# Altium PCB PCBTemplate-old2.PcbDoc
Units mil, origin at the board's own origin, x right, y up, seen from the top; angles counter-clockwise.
Board outline 6000 x 4000 mil, 4 copper layers (Top Layer, Internal Plane 1, Internal Plane 2, Bottom Layer); 0 components, 0 nets, 1 pads, 0 vias.
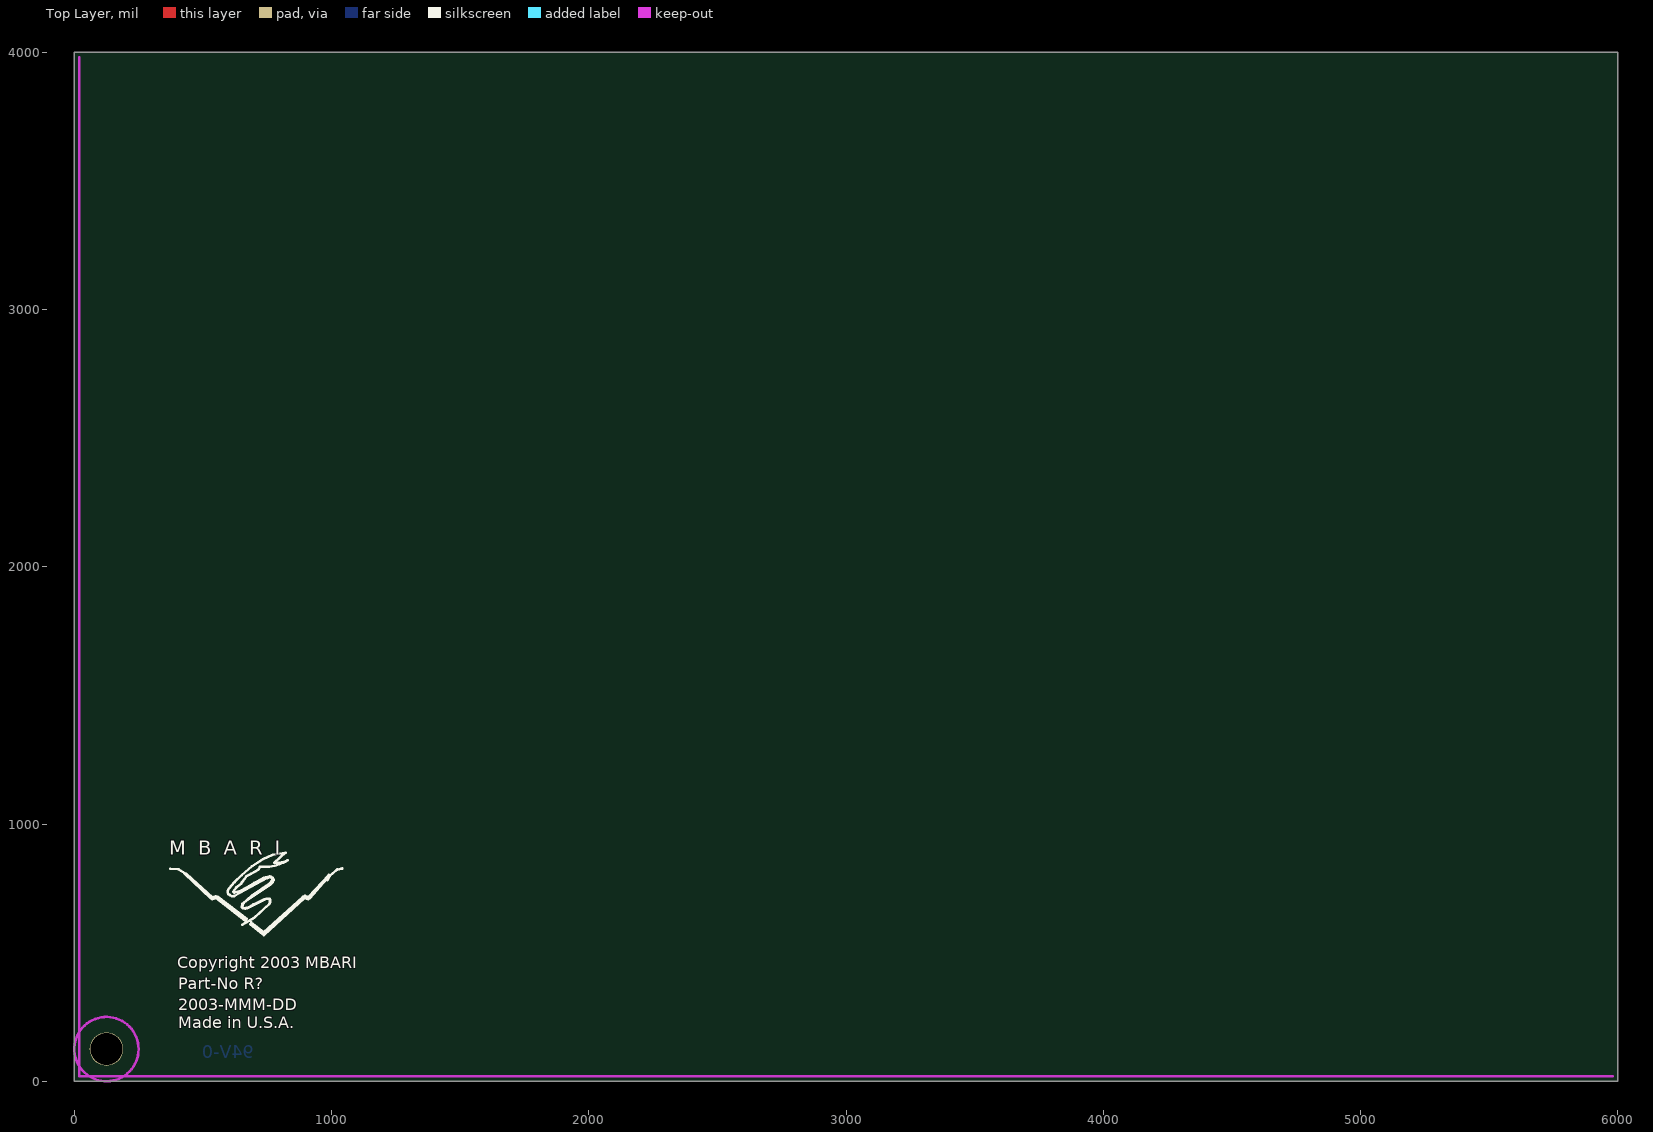
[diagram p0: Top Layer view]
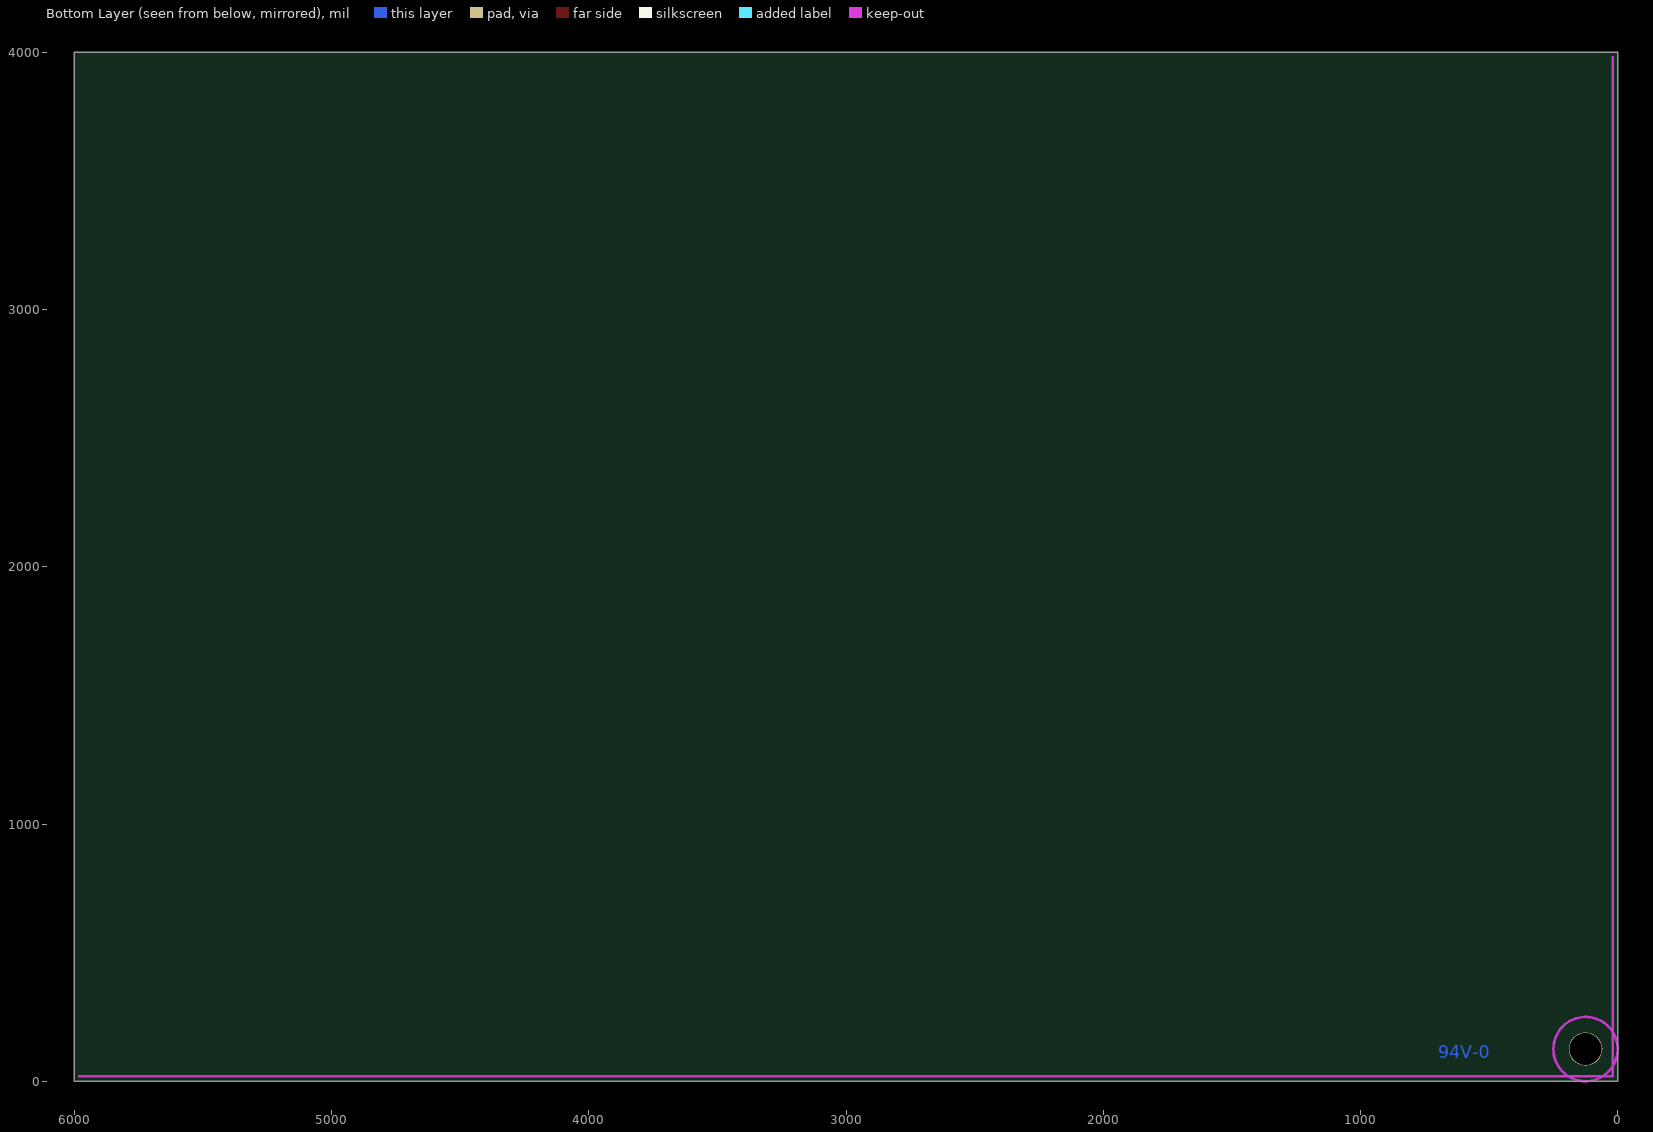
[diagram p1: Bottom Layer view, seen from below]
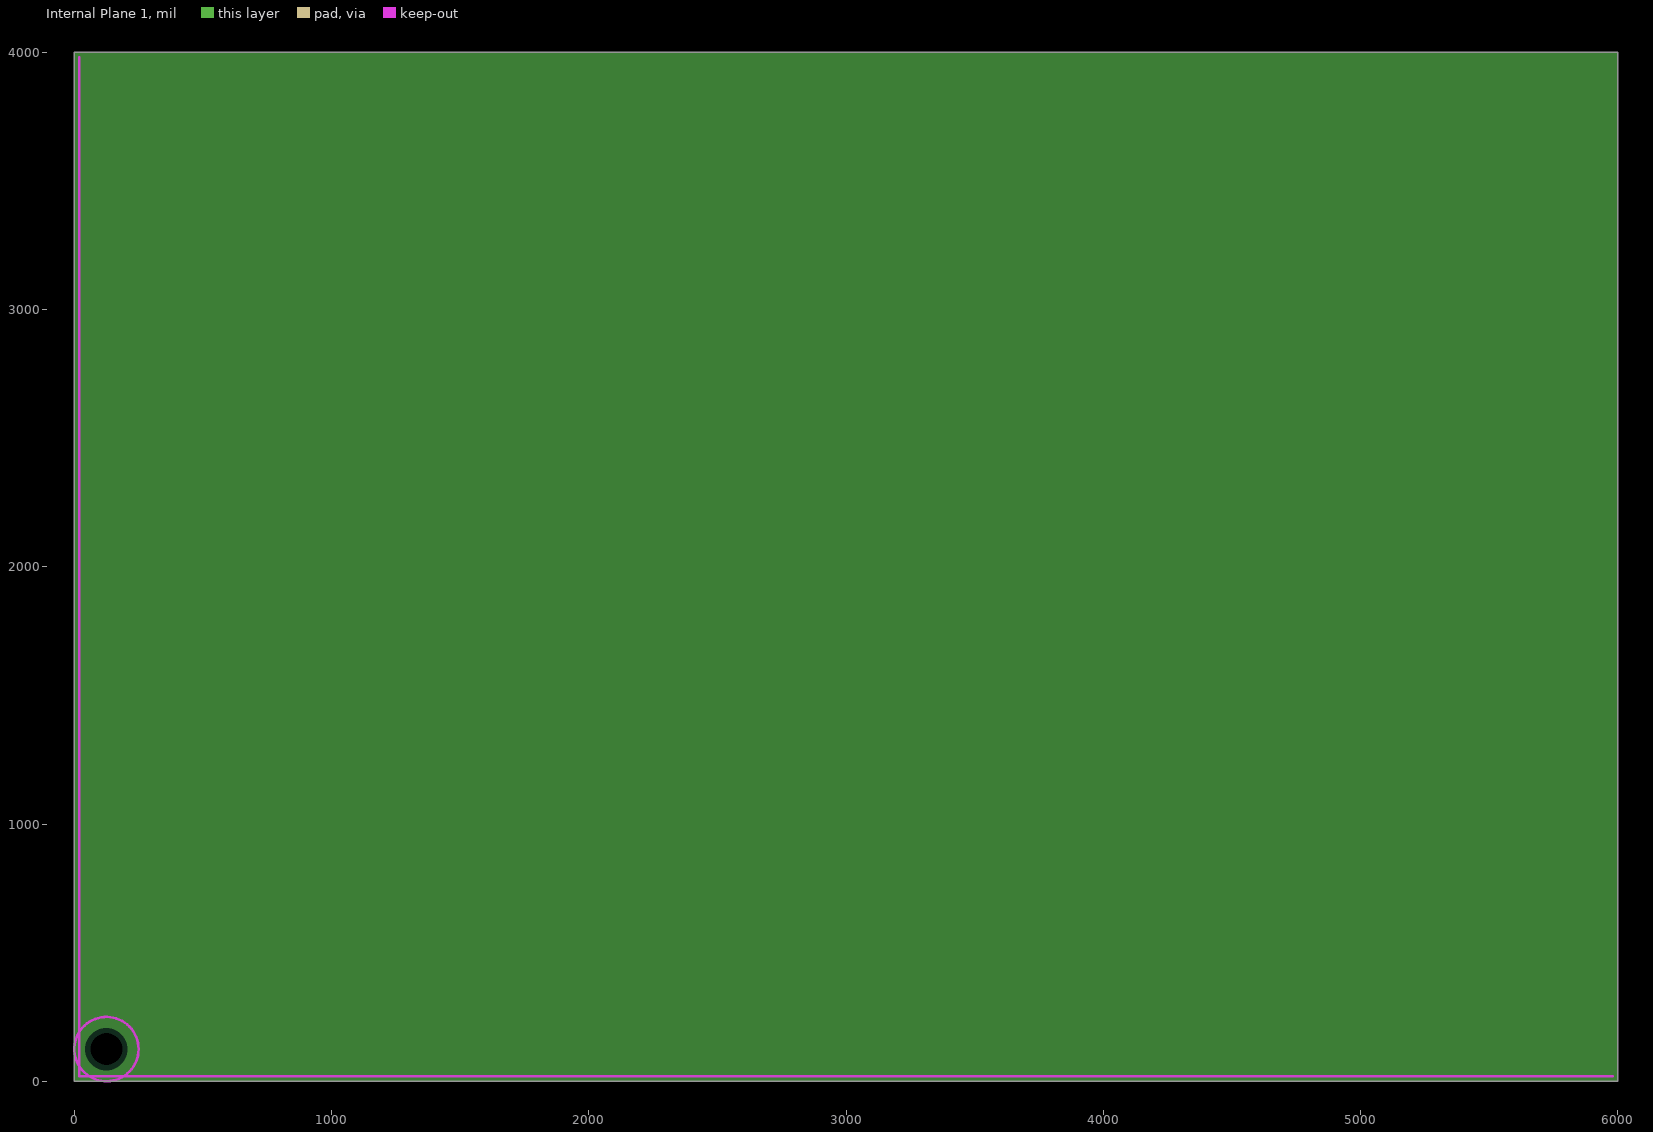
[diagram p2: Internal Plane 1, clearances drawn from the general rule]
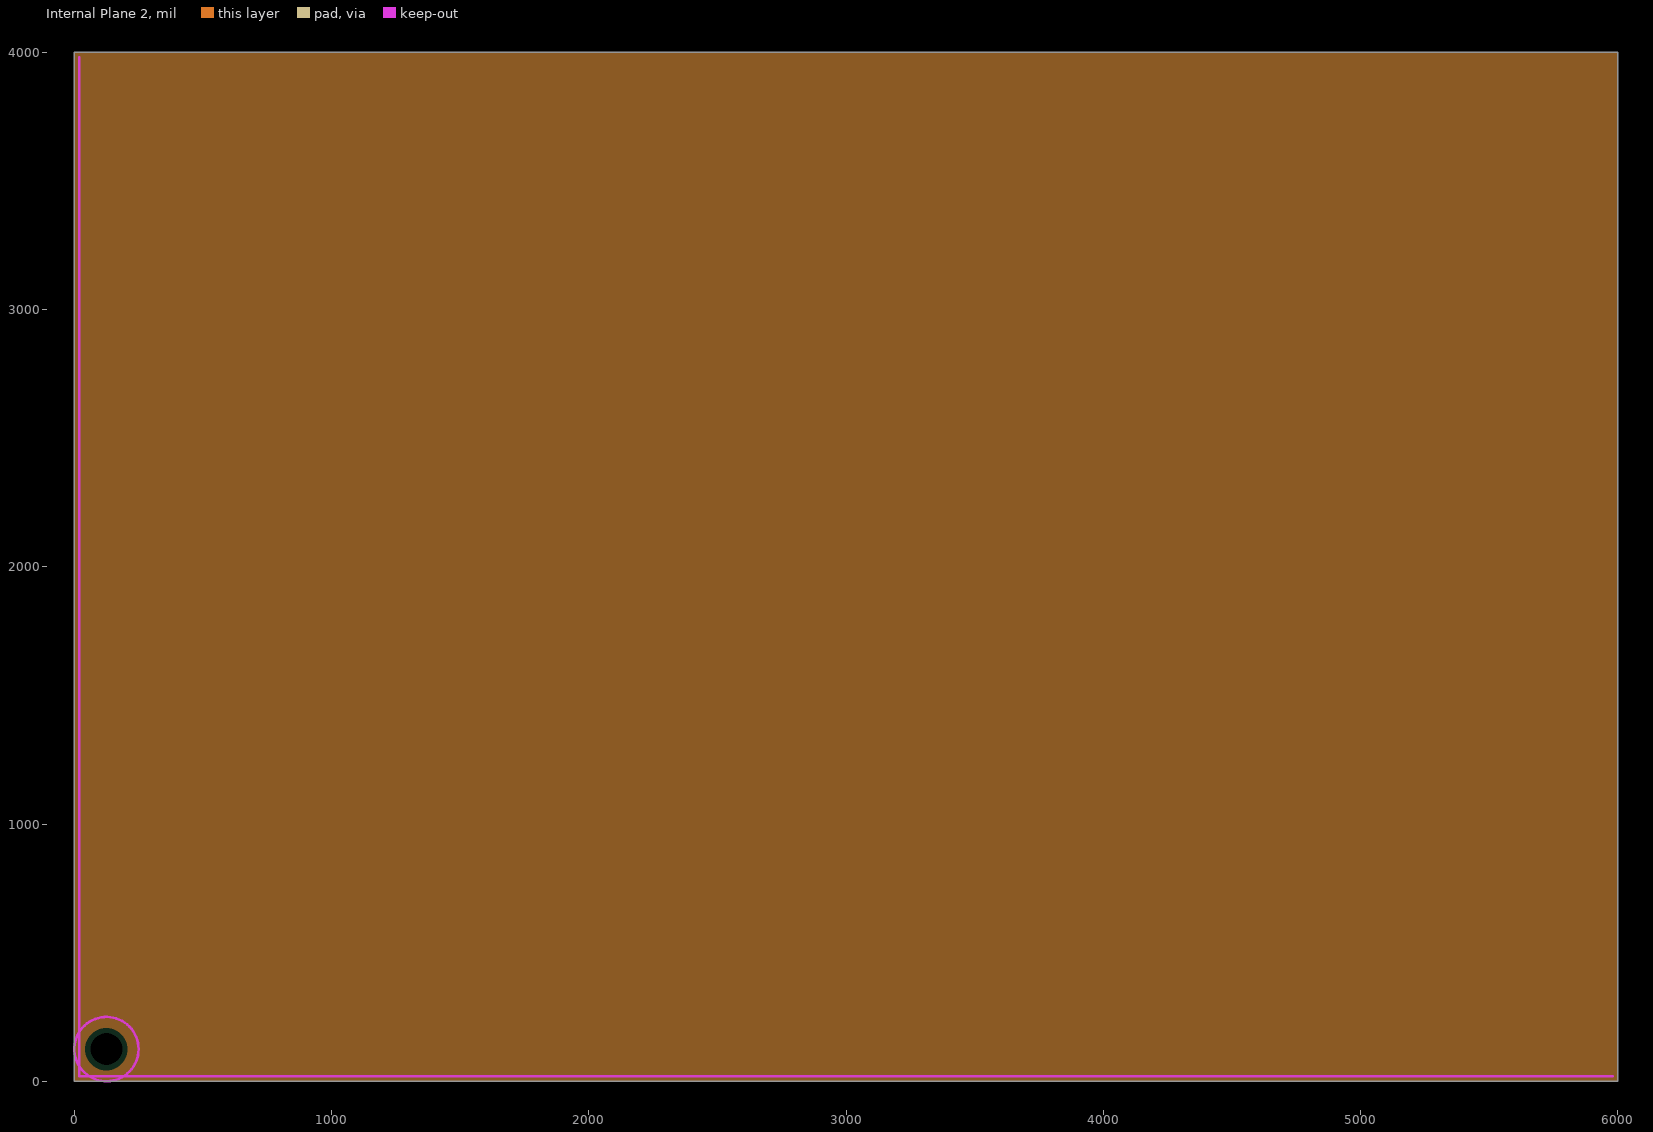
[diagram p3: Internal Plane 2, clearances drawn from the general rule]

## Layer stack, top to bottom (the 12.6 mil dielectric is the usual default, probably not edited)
Top Layer: signal copper 1.4
Dielectric: dielectric 12.6, FR-4, Dk 4.8
Internal Plane 1: plane copper 1.4
Dielectric: dielectric 12.6, FR-4, Dk 4.8
Internal Plane 2: plane copper 1.4
Dielectric: dielectric 12.6, FR-4, Dk 4.8
Bottom Layer: signal copper 1.4

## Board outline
0,0 0,4000 6000,4000 6000,0

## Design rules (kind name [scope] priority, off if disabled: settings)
Clearance [All] p1: gap=13
ComponentClearance [All] p1: gap=10 collisioncheckmode=0
FanoutControl Fanout_Small [(CompPinCount < 5)] p1: bgadir=Out bgaviamode=Centered fanoutstyle=Auto fanoutdirection=OutThenIn viagrid=1 // Fanout_Small (Default Rule)
FanoutControl Fanout_Default [All] p2: bgadir=Out bgaviamode=Centered fanoutstyle=Auto fanoutdirection=Alternating viagrid=1 // Fanout_Default (Default Rule)
FanoutControl Fanout_BGA [IsBGA] p4: bgadir=Out bgaviamode=Centered fanoutstyle=Auto fanoutdirection=Alternating viagrid=1 // Fanout_BGA (Default Rule)
FanoutControl Fanout_LCC [IsLCC] p5: bgadir=Out bgaviamode=Centered fanoutstyle=Auto fanoutdirection=Alternating viagrid=1 // Fanout_LCC (Default Rule)
HoleSize [All] p1: absolutevalues=TRUE maxlimit=152 minlimit=1 maxpercent=80.000 minpercent=20.000
PlaneClearance [All] p1: clearance=20
PlaneConnect [All] p1: planeconnectstyle=Relief reliefexpansion=20 reliefentries=4 reliefconductorwidth=10 reliefairgap=10
PolygonConnect [All] p1: connectstyle=Relief reliefconductorwidth=10 reliefentries=4 polygonreliefangle="90 Angle"
RoutingLayers [All] p1: top layer=Horizontal bottom layer=Vertical
RoutingVias [All] p1: holewidth=35 width=52 viastyle="Through Hole" minholewidth=28 minwidth=32 maxholewidth=86 maxwidth=72
SolderMaskExpansion [All] p1: expansion=4
TestPointUsage [All] p1: valid=0 allowmultiple=FALSE
Testpoint [All] p1: side=15 testpointundercomponent=TRUE minsize=40 maxsize=100 preferedsize=60 minholesize=0 maxholesize=40 preferedholesize=32 testpointgrid=1 style=1023 order=-539222988
Width [All] p1: maxlimit=250 minlimit=8 preferedwidth=12 toplayer_prefwidth=10 bottomlayer_prefwidth=10 minimp=50.000000 maximp=50.000000 favimp=50.000000
9 further rules are at their usual default settings.

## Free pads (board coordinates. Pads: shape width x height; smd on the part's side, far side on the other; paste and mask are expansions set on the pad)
  round 130 hole 125: 0(125,125)

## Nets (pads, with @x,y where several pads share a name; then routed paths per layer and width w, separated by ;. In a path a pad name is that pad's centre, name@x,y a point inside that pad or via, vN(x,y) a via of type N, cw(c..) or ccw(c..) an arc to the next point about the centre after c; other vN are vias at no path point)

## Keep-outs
Keep-Out Layer:
  circle w10: c125,125 r125
  lines w10: 20,3980 20,20 5980,20
  text ".GKO" at 15640,-540 h90

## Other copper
Top Layer:
  text ".GTL" at 15640,-540 h90
Bottom Layer:
  text "94V-0" at 697.07,88.79 h50
  text ".GBL" at 15640,-540 h90

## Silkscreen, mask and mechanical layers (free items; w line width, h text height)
Top Overlay:
  lines w10: 373,826 405,824 436,806 537,715 550,719 557,718 671,631 ; 428,808 531,711 ; 536,708 551,712 666,624 ; 653,608 699,635 758,689 761,696 761,706 759,709 753,710 746,710 ; 684,610 731,573 ; 688,617 736,579 888,717 897,721 911,716 990,802 993,797 1022,823 1042,827 ; 760,695 760,703 758,707 753,709 746,710 ; 894,713 909,708 ; 916,712 981,785 ; 984,782 990,791 ; 746,710 672,672 664,670 657,672 653,679 654,685 658,693 669,701 764,766 772,775 775,782 773,787 771,791 767,793 760,793 750,790 622,720 612,719 604,724 599,728 596,735 597,741 601,749 623,774 651,801 690,835 733,863 772,881 821,889 778,850 795,850 824,855 829,859 812,849 796,844 780,838 757,833 722,833 715,822 702,814 687,807 669,797 647,767 629,752 618,737 622,733 652,743 700,771 736,791 760,797 766,795 770,784 759,768 691,721 653,689 652,677 656,672 679,676 696,687 739,707 746,710 ; 737,568 896,713 737,568
  text "M  B  A  R  I" at 370,880 h55
  text "Copyright 2003 MBARI" at 400,440 h45
  text "Part-No R?" at 405,356.68 h45
  text "2003-MMM-DD" at 405,276.68 h45
  text "Made in U.S.A." at 405,206.68 h45
  text ".GTO" at 15640,-540 h90
Bottom Overlay:
  text ".GBO" at 15650,-540 h90
Top Solder:
  text ".GTS" at 15640,-540 h90
Bottom Solder:
  text ".GBS" at 15640,-540 h90
Drill Guide:
  text ".GG1" at 15650,-540 h90
Mechanical 4:
  lines w10: 0,4000 0,0 6000,0
Mechanical 16:
  lines w5: -800,1950 -600,1950 ; -800,4700 -600,4700 ; -800,7450 -600,7450 ; 2035,-800 2035,-600 ; 2035,10000 2035,10200 ; 4865,-800 4865,-600 ; 4865,10000 4865,10200 ; 7700,-800 7700,-600 ; 7700,10000 7700,10200 ; 10100,0 16000,0 ; 10530,-800 10530,-600 ; 10530,10000 10530,10200 ; 11500,-300 16000,-300 ; 11500,300 13000,300 ; 13000,-600 13000,0 13000,600 ; 13365,-800 13365,-600 ; 13365,10000 13365,10200 ; 15100,-600 15100,0 ; 16000,1950 16200,1950 ; 16000,4700 16200,4700 ; 16000,7450 16200,7450 ; 11500,-600 11500,600 ; 11500,-600 16000,-600 ; 11500,-600 10100,-600 10100,600 11500,600 ; 11500,600 13000,600 ; 13000,600 16000,600 16000,-600 ; 16000,-600 16000,10000 -600,10000 -600,-600 16000,-600 ; -800,-800 16200,-800 16200,10200 -800,10200 -800,-800
  lines w10: 10433,446 10465,444 10496,426 10597,335 10610,339 10617,338 10731,251 ; 10488,428 10591,331 ; 10596,328 10611,332 10726,244 ; 10713,228 10759,255 10818,309 10821,316 10821,326 10819,329 10813,330 10806,330 ; 10744,230 10791,193 ; 10748,237 10796,199 10948,337 10957,341 10971,336 11050,422 11053,417 11082,443 11102,447 ; 10820,315 10820,323 10818,327 10813,329 10806,330 ; 10954,333 10969,328 ; 10976,332 11041,405 ; 11044,402 11050,411 ; 10806,330 10732,292 10724,290 10717,292 10713,299 10714,305 10718,313 10729,321 10824,386 10832,395 10835,402 10833,407 10831,411 10827,413 10820,413 10810,410 10682,340 10672,339 10664,344 10659,348 10656,355 10657,361 10661,369 10683,394 10711,421 10750,455 10793,483 10832,501 10881,509 10838,470 10855,470 10884,475 10889,479 10872,469 10856,464 10840,458 10817,453 10782,453 10775,442 10762,434 10747,427 10729,417 10707,387 10689,372 10678,357 10682,353 10712,363 10760,391 10796,411 10820,417 10826,415 10830,404 10819,388 10751,341 10713,309 10712,297 10716,292 10739,296 10756,307 10799,327 10806,330 ; 10797,188 10956,333 10797,188
  text "1" at 601.34,10065 h70
  text "2" at 3427,10065 h70
  text "3" at 6252,10065 h70
  text "4" at 9093.01,10065 h70
  text "5" at 11927,10065 h70
  text "6" at 14762,10065 h70
  text "A" at -725,8822 h70
  text "A" at 16075,8822 h70
  text "B" at -725,6088.02 h70
  text "B" at 16075,6088.02 h70
  text "C" at -725,3307 h70
  text "C" at 16075,3307 h70
  text "M  B  A  R  I" at 10430,500 h55
  text "ENGINEER:" at 11550,500 h45
  text "TITLE:" at 13050,500 h45
  text "D" at -725,485 h70
  text "D" at 16075,485 h70
  text "Mark Sibenac" at 12060,470 h70
  text "Title I" at 13400,380 h90
  text "1 831 775 2028" at 12050,330 h60
  text "PCB DESIGNER:" at 11550,205 h45
  text "Title II" at 13420,160 h90
  text "Copyright      2003" at 10280,150 h60
  text "Monterey Bay Aquarium Research Institute" at 10150,40 h45
  text "DATE:" at 11550,-100 h45
  text "PART NO.:" at 13050,-100 h45
  text "REV:" at 15150,-100 h45
  text ".PRINT_DATE" at 11600,-220 h70
  text "1" at 15430,-220 h90
  text "Part Number" at 13410,-230 h60
  text "M.B.A.R.I." at 10180,-240 h100
  text "7700 Sandholdt Rd." at 10170,-340 h60
  text "FILE NAME:" at 11550,-400 h45
  text "DWG NO:" at 13050,-400 h45
  text "GERBER:" at 15150,-400 h45
  text "Moss Landing, CA 95039" at 10170,-450 h60
  text "DWG Number" at 13410,-490 h60
  text ".PCB_FILE_NAME_NO_PATH" at 11600,-520 h70
  text ".GM16" at 15260,-530 h70
  text "Fax: 1 831 775 1646" at 10170,-550 h60
  text "1" at 601.34,-735 h70
  text "2" at 3427,-735 h70
  text "3" at 6252,-735 h70
  text "4" at 9093.01,-735 h70
  text "5" at 11927,-735 h70
  text "6" at 14762,-735 h70
Drill Drawing:
  text ".LEGEND" at 10145,870 h60
  text "Drill Drawing." at 10125,780 h60
  text ".GD1" at 15645,-540 h90

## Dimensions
125,125 to 0,0 on Mechanical 4
125,125 to 0,0 on Mechanical 4
0,4000 to 0,0 on Mechanical 4
0,0 to 6000,0 on Mechanical 4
